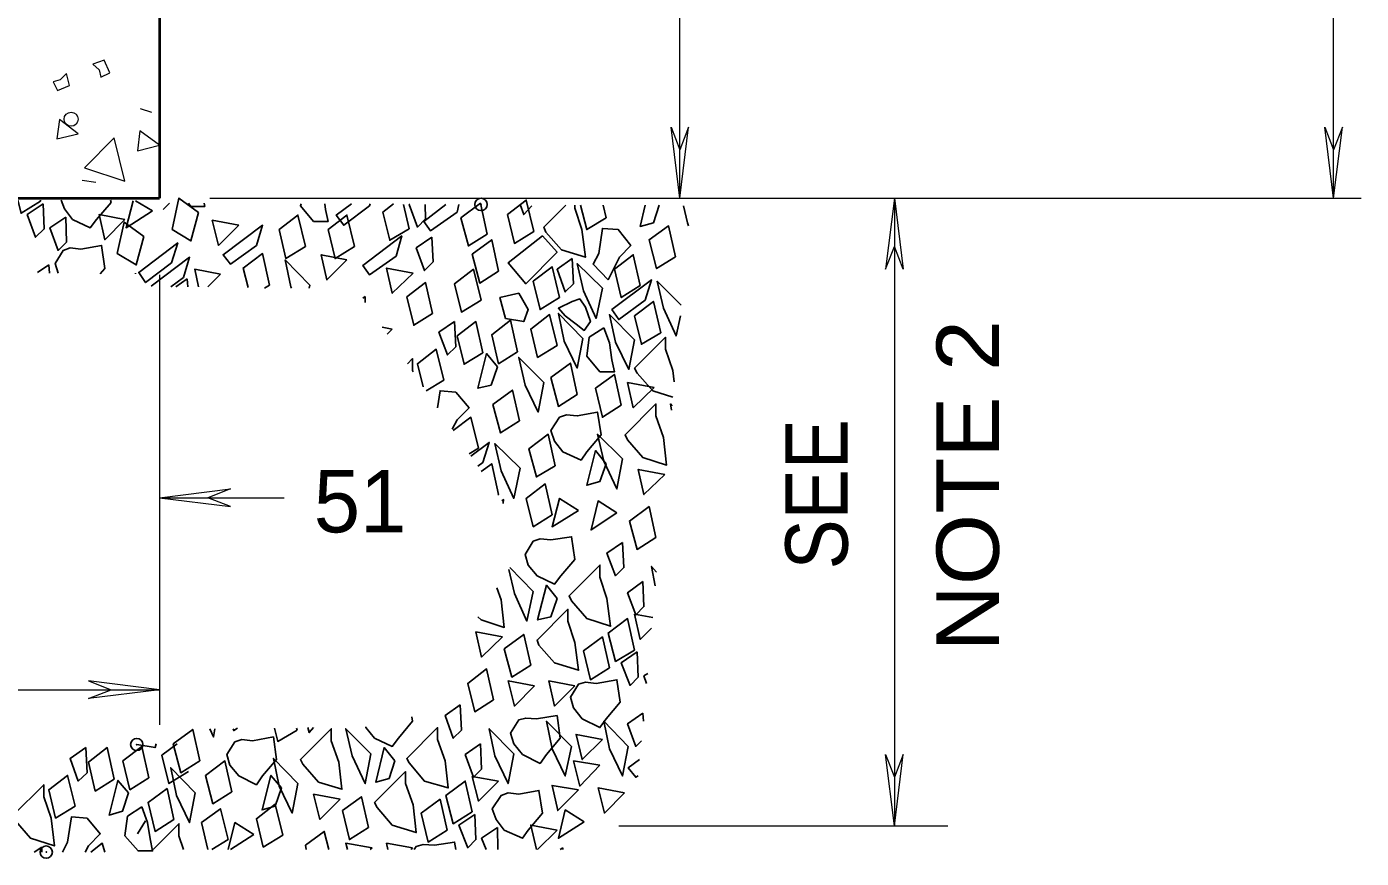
# Model space of a CAD drawing. Extents: x 312583 to 312854, y 144419 to 144597.
# Drawn here: x 312724.13 to 312740.39, y 144443.57 to 144453.7 of the extents above; entities that cross this region are included whole.
import ezdxf

# ---------------------------------------------------------------- set-up
doc = ezdxf.new("R2010")
doc.units = 0
doc.header["$LTSCALE"] = 0.3
doc.header["$PDMODE"] = 32
doc.header["$PDSIZE"] = 0.15
doc.layers.add('1', color=7, linetype='Continuous', lineweight=25)
doc.layers.add('2', color=7, linetype='Continuous', lineweight=13)

msp = doc.modelspace()

# ---------------------------------------------------------------- linework, layer by layer
at = {"layer": '1', "lineweight": 40}
for p in [(312725.751, 144497.14), (312697.001, 144451.6154)]:
    msp.add_line(p, (312725.751, 144451.6154), dxfattribs=at)
at = {"layer": '1'}
for p, q in [((312724.302, 144451.577), (312724.302, 144451.5924)), ((312725.4597, 144451.5847), (312725.6667, 144451.462)), ((312725.8737, 144451.554), (312725.797, 144451.4774)), ((312728.3194, 144451.5464), (312728.3117, 144451.5234)), ((312728.7947, 144451.2397), (312728.7257, 144451.5387)), ((312729.4004, 144451.5387), (312729.3774, 144451.4467)), ((312729.6687, 144451.5387), (312729.661, 144451.5387)), ((312730.811, 144451.531), (312730.811, 144451.4927)), ((312731.1944, 144451.3777), (312731.156, 144451.531)), ((312724.2637, 144450.7107), (312724.4017, 144450.8027)), ((312724.4017, 144450.8027), (312724.4094, 144450.703)), ((312725.4597, 144450.6954), (312725.4597, 144450.703)), ((312726.0424, 144450.6494), (312725.889, 144450.5344)), ((312726.4947, 144450.6877), (312726.3414, 144450.5344)), ((312725.9504, 144450.5344), (312726.0884, 144450.634)), ((312726.0884, 144450.634), (312726.096, 144450.5344)), ((312727.0314, 144450.519), (312727.0927, 144450.5574)), ((312727.5757, 144450.519), (312727.5834, 144450.5574)), ((312728.2274, 144450.3964), (312728.258, 144450.4194)), ((312728.258, 144450.4194), (312728.258, 144450.3427)), ((312728.465, 144450.0437), (312728.5877, 144450.0207)), ((312728.5877, 144450.0207), (312728.5264, 144449.9594)), ((312728.833, 144449.5147), (312728.8407, 144449.4994)), ((312729.0017, 144449.2694), (312729.2164, 144449.3997)), ((312731.8, 144448.9627), (312731.892, 144448.702)), ((312729.523, 144448.5027), (312729.638, 144448.5717)), ((312729.6917, 144448.3954), (312729.6304, 144448.3494)), ((312729.8757, 144447.9967), (312729.8834, 144448.0044)), ((312730.305, 144446.8237), (312730.0214, 144447.115)), ((312731.639, 144445.344), (312731.6467, 144445.2444)), ((312727.43, 144445.137), (312727.4224, 144445.16)), ((312725.4827, 144443.872), (312725.5824, 144444.033)), ((312725.9887, 144443.849), (312726.0424, 144443.6804)), ((312726.901, 144443.8644), (312726.6174, 144443.6804)), ((312729.868, 144443.9487), (312729.8757, 144443.6804)), ((312730.5964, 144443.918), (312730.3587, 144443.6804)), ((312724.2254, 144443.6497), (312724.3174, 144443.711)), ((312724.3174, 144443.711), (312724.3174, 144443.6497)), ((312726.3874, 144443.6804), (312726.5867, 144443.803)), ((312728.3424, 144443.7034), (312728.3194, 144443.6804)), ((312728.833, 144443.7034), (312728.8177, 144443.6804)), ((312730.6347, 144443.6804), (312730.6654, 144443.7034)), ((312730.6654, 144443.7034), (312730.6654, 144443.6804)), ((312724.3787, 144443.6497), (312724.371, 144443.6497))]:
    msp.add_line(p, q, dxfattribs=at)
for points in [[(312724.026, 144451.5924), (312724.0644, 144451.4314), (312724.302, 144451.577)], [(312724.9844, 144451.3547), (312724.9077, 144451.255), (312724.693, 144451.3547), (312724.5934, 144451.485), (312724.555, 144451.5924)], [(312725.153, 144451.5924), (312725.1607, 144451.5617), (312724.9844, 144451.3547)], [(312725.6667, 144451.462), (312725.3447, 144451.255), (312725.429, 144451.5847)], [(312726.2954, 144451.554), (312726.303, 144451.5157), (312726.1344, 144451.5157), (312726.1037, 144451.554)], [(312727.7674, 144451.5464), (312727.775, 144451.4774), (312727.8057, 144451.3317), (312727.6294, 144451.3317), (312727.4684, 144451.5234), (312727.476, 144451.5464)], [(312728.3117, 144451.5234), (312727.9974, 144451.2857), (312727.9054, 144451.4084), (312728.0894, 144451.5464)], [(312728.603, 144451.5464), (312728.4727, 144451.4467), (312728.557, 144451.1017), (312728.7947, 144451.2397)], [(312728.9864, 144451.5387), (312728.994, 144451.3624), (312728.8944, 144451.2627), (312728.7947, 144451.5387), (312728.8024, 144451.5387)], [(312729.3774, 144451.4467), (312729.0554, 144451.2167), (312728.971, 144451.3317), (312729.2394, 144451.5387)], [(312730.2897, 144451.5234), (312730.19, 144451.416), (312730.144, 144451.5387)], [(312730.811, 144451.4927), (312730.8954, 144451.232), (312730.9414, 144450.8947), (312730.65, 144450.9867), (312730.4584, 144451.2014), (312730.4354, 144451.2627), (312730.7037, 144451.531)], [(312730.88, 144451.531), (312730.9567, 144451.232), (312731.1944, 144451.3777)], [(312731.8384, 144451.531), (312731.7694, 144451.3164), (312731.6084, 144451.2704), (312731.6697, 144451.531)], [(312732.1374, 144451.5234), (312732.1834, 144451.3164), (312732.1987, 144451.278)], [(312724.5167, 144450.703), (312724.4784, 144450.818), (312724.578, 144450.979), (312724.6624, 144451.0097), (312724.7927, 144450.9944), (312725.0457, 144451.0404), (312725.084, 144450.7567), (312725.0304, 144450.6954)], [(312725.6514, 144450.542), (312726.119, 144450.8947), (312726.0424, 144450.6494)], [(312727.0927, 144450.5574), (312727.0084, 144450.9407), (312726.7707, 144450.7644), (312726.832, 144450.5267)], [(312727.5834, 144450.5574), (312727.2844, 144450.864), (312727.3534, 144450.5344), (312727.361, 144450.519)], [(312726.2264, 144450.5344), (312726.1804, 144450.749), (312726.4947, 144450.6877)], [(312732.1067, 144450.312), (312731.8154, 144450.6034), (312731.892, 144450.2737), (312732.0454, 144449.9364), (312732.099, 144450.1817)], [(312732.007, 144449.1927), (312731.7617, 144449.2694), (312731.57, 144449.484), (312731.5394, 144449.5454), (312731.915, 144449.921), (312731.915, 144449.7754)], [(312729.2164, 144449.3997), (312729.1244, 144449.7754), (312728.8944, 144449.599), (312728.9634, 144449.3154)], [(312731.915, 144449.7754), (312732.007, 144449.5147), (312732.0224, 144449.3767)], [(312728.7717, 144449.599), (312728.833, 144449.6604), (312728.833, 144449.5147)], [(312729.316, 144448.8017), (312729.3774, 144448.9167), (312729.523, 144449.0624), (312729.362, 144449.254), (312729.1704, 144449.2694), (312729.1397, 144449.0624)], [(312731.9304, 144448.3647), (312731.9304, 144448.3647), (312731.639, 144448.4567), (312731.455, 144448.6714), (312731.4244, 144448.7327), (312731.8, 144449.1084), (312731.8, 144448.9627)], [(312731.9994, 144449.0854), (312731.9764, 144449.1084), (312731.9917, 144449.0317)], [(312729.638, 144448.5717), (312729.546, 144448.9474), (312729.3314, 144448.7864)], [(312731.892, 144448.702), (312731.9304, 144448.3647), (312731.9304, 144448.3647)], [(312729.546, 144448.472), (312729.7684, 144448.6407), (312729.6917, 144448.3954)], [(312729.8834, 144448.0044), (312729.799, 144448.38), (312729.6687, 144448.288)], [(312729.9217, 144447.9277), (312729.9447, 144447.943), (312729.937, 144447.897)], [(312730.006, 144447.092), (312730.075, 144446.8007), (312730.2284, 144446.4634), (312730.305, 144446.8237)], [(312731.8077, 144447.0614), (312731.7464, 144447.1304), (312731.7924, 144446.8927)], [(312729.8604, 144446.8697), (312729.914, 144446.724), (312729.9524, 144446.3867), (312729.6687, 144446.4787), (312729.6304, 144446.517)], [(312731.7464, 144446.379), (312731.6084, 144446.241), (312731.5394, 144446.5477), (312731.7617, 144446.5094)], [(312731.685, 144445.7044), (312731.6544, 144445.7964), (312731.7004, 144445.827)], [(312728.8254, 144445.298), (312728.833, 144445.2444), (312728.6644, 144445.0374)], [(312731.6237, 144445.0067), (312731.5547, 144444.9377), (312731.455, 144445.2137), (312731.639, 144445.344)], [(312726.3644, 144445.1524), (312726.4104, 144445.0527), (312726.4257, 144445.1524)], [(312726.648, 144445.1524), (312726.6557, 144445.1294), (312726.7017, 144445.16)], [(312727.154, 144445.16), (312727.1924, 144444.999), (312727.43, 144445.137)], [(312727.6294, 144445.1677), (312727.5757, 144445.1064), (312727.5604, 144445.1677)], [(312728.6644, 144445.0374), (312728.5877, 144444.9377), (312728.373, 144445.0374), (312728.2657, 144445.1677), (312728.2657, 144445.1754)], [(312725.7127, 144444.9684), (312725.6974, 144444.9224), (312725.475, 144444.9607)], [(312725.9657, 144444.9684), (312725.7817, 144444.8304), (312725.866, 144444.4854), (312726.1037, 144444.631)], [(312731.5854, 144444.5774), (312731.5547, 144444.562), (312731.4627, 144444.677), (312731.6007, 144444.7767)], [(312726.5867, 144443.803), (312726.4947, 144444.1787), (312726.2647, 144444.01), (312726.3414, 144443.6804)], [(312724.8464, 144443.6497), (312724.8847, 144443.7264), (312725.0304, 144443.872), (312724.8694, 144444.0637), (312724.6777, 144444.079), (312724.6317, 144443.7724), (312724.5704, 144443.6497)], [(312725.6744, 144443.6804), (312725.9887, 144443.9947), (312725.9887, 144443.849)], [(312726.5867, 144443.6804), (312726.671, 144444.01), (312726.901, 144443.8644)], [(312727.8134, 144443.6804), (312727.7597, 144443.9027), (312727.5297, 144443.734), (312727.5374, 144443.6804)], [(312729.73, 144443.6804), (312729.6764, 144443.8184), (312729.868, 144443.9487)], [(312730.3434, 144443.6804), (312730.2744, 144443.9794), (312730.5964, 144443.918)], [(312725.084, 144443.6497), (312725.0534, 144443.757), (312724.9154, 144443.6497)], [(312728.0434, 144443.6804), (312728.0204, 144443.757), (312728.3424, 144443.7034)], [(312728.534, 144443.6804), (312728.5187, 144443.757), (312728.833, 144443.7034)], [(312728.856, 144443.6804), (312728.879, 144443.7187), (312728.9634, 144443.7417), (312729.1014, 144443.734), (312729.3467, 144443.7724), (312729.362, 144443.6804)]]:
    msp.add_lwpolyline(points, dxfattribs=at)
for points in [[(312724.3327, 144451.5464), (312724.348, 144451.2397), (312724.2407, 144451.14), (312724.141, 144451.416)], [(312725.9044, 144451.232), (312725.9887, 144451.6154), (312726.2264, 144451.439), (312726.1344, 144451.094)], [(312729.7454, 144451.1784), (312729.661, 144451.554), (312729.4234, 144451.3777), (312729.5154, 144451.0327)], [(312730.3127, 144451.209), (312730.2207, 144451.5924), (312729.9907, 144451.416), (312730.075, 144451.0634)], [(312724.6087, 144451.3854), (312724.6164, 144451.0787), (312724.5167, 144450.979), (312724.417, 144451.255)], [(312725.3294, 144451.3547), (312725.084, 144451.1094), (312725.015, 144451.416)], [(312725.2374, 144450.9407), (312725.3217, 144451.324), (312725.5594, 144451.1477), (312725.4674, 144450.8027)], [(312726.717, 144451.2857), (312726.4717, 144451.0404), (312726.395, 144451.347)], [(312727.5297, 144451.025), (312727.4377, 144451.4084), (312727.2077, 144451.232), (312727.292, 144450.8794)], [(312728.1277, 144451.025), (312728.0357, 144451.4084), (312727.8057, 144451.232), (312727.89, 144450.8794)], [(312726.9317, 144451.0404), (312726.6174, 144450.8104), (312726.5254, 144450.9254), (312727.0084, 144451.2857)], [(312728.6337, 144450.91), (312728.3117, 144450.68), (312728.2274, 144450.795), (312728.7027, 144451.1554)], [(312729.0707, 144451.14), (312729.086, 144450.841), (312728.9787, 144450.7337), (312728.879, 144451.0097)], [(312730.42, 144451.1554), (312730.5964, 144450.956), (312730.213, 144450.5727), (312729.9984, 144450.8257)], [(312731.2174, 144450.6187), (312731.3554, 144450.8947), (312731.4934, 144451.0404), (312731.34, 144451.232), (312731.1484, 144451.2474), (312731.1024, 144450.9407), (312731.0334, 144450.8104)], [(312732.0377, 144450.9024), (312731.9534, 144451.278), (312731.7157, 144451.1094), (312731.8077, 144450.7567)], [(312725.8967, 144450.8257), (312725.5824, 144450.588), (312725.498, 144450.7107), (312725.9734, 144451.071)], [(312729.8834, 144450.726), (312729.799, 144451.1094), (312729.5614, 144450.933), (312729.6534, 144450.5804)], [(312728.0357, 144450.864), (312727.7904, 144450.6187), (312727.7214, 144450.9254)], [(312730.7804, 144450.8794), (312730.7957, 144450.5727), (312730.696, 144450.473), (312730.5964, 144450.749)], [(312731.1484, 144450.519), (312730.8417, 144450.818), (312730.9184, 144450.4884), (312731.0717, 144450.151)], [(312731.6084, 144450.5497), (312731.524, 144450.9254), (312731.294, 144450.749), (312731.3784, 144450.404)], [(312728.8407, 144450.703), (312728.5877, 144450.4577), (312728.5187, 144450.7644)], [(312729.6687, 144450.3734), (312729.5767, 144450.749), (312729.3467, 144450.5727), (312729.431, 144450.2277)], [(312730.627, 144450.404), (312730.535, 144450.7797), (312730.305, 144450.6034), (312730.3894, 144450.2584)], [(312729.0784, 144450.2124), (312728.994, 144450.588), (312728.764, 144450.4117), (312728.8484, 144450.0667)], [(312731.6697, 144450.3734), (312731.3477, 144450.1357), (312731.2634, 144450.2584), (312731.7464, 144450.6187)], [(312730.1287, 144450.4577), (312730.2437, 144450.2584), (312730.19, 144450.1127), (312729.9677, 144450.151), (312729.8987, 144450.404)], [(312730.7804, 144450.358), (312730.8724, 144450.3887), (312730.9414, 144450.289), (312731.0027, 144450.1127), (312730.926, 144450.0054), (312730.8264, 144450.082), (312730.696, 144450.1817), (312730.6117, 144450.2737)], [(312731.8614, 144449.9747), (312731.7694, 144450.358), (312731.5394, 144450.1817), (312731.6237, 144449.8367)], [(312730.5964, 144449.8214), (312730.5044, 144450.197), (312730.2744, 144450.0207), (312730.3587, 144449.6757)], [(312730.9107, 144449.9057), (312730.6117, 144450.2124), (312730.6807, 144449.875), (312730.8417, 144449.5454)], [(312731.5394, 144449.8904), (312731.2327, 144450.197), (312731.3094, 144449.8597), (312731.4704, 144449.53)], [(312729.3467, 144450.1127), (312729.362, 144449.806), (312729.2624, 144449.7064), (312729.155, 144449.9824)], [(312729.6917, 144449.7294), (312729.6074, 144450.1127), (312729.3774, 144449.9364), (312729.4617, 144449.5914)], [(312730.1134, 144449.7447), (312730.029, 144450.128), (312729.799, 144449.9517), (312729.8834, 144449.599)], [(312731.1637, 144450.036), (312731.2327, 144449.852), (312731.2634, 144449.645), (312731.294, 144449.4994), (312731.1177, 144449.4994), (312730.9567, 144449.691), (312730.9874, 144449.921)], [(312729.868, 144449.5607), (312729.7914, 144449.3384), (312729.6304, 144449.3), (312729.7377, 144449.7217)], [(312730.4354, 144449.369), (312730.1287, 144449.6757), (312730.2054, 144449.3384), (312730.3664, 144449.0087)], [(312730.8417, 144449.2234), (312730.7574, 144449.6067), (312730.5197, 144449.4304), (312730.6117, 144449.0777)], [(312731.3784, 144449.093), (312731.294, 144449.4687), (312731.064, 144449.3), (312731.1484, 144448.9474)], [(312731.777, 144449.3077), (312731.524, 144449.0624), (312731.455, 144449.369)], [(312730.1364, 144448.9014), (312730.052, 144449.277), (312729.8144, 144449.1007), (312729.9064, 144448.7557)], [(312730.9567, 144448.5257), (312730.8877, 144448.426), (312730.6654, 144448.5257), (312730.5657, 144448.656), (312730.5197, 144448.7864), (312730.627, 144448.9474), (312730.7114, 144448.978), (312730.8417, 144448.9627), (312731.087, 144449.0087), (312731.133, 144448.7327)], [(312730.5734, 144448.357), (312730.489, 144448.7404), (312730.2514, 144448.564), (312730.3434, 144448.219)], [(312731.3937, 144448.4414), (312731.087, 144448.7404), (312731.1637, 144448.4107), (312731.3247, 144448.0734)], [(312730.144, 144448.3264), (312729.8374, 144448.6254), (312729.914, 144448.2957), (312730.0674, 144447.9584)], [(312731.1944, 144448.38), (312731.1177, 144448.1654), (312730.9567, 144448.1194), (312731.064, 144448.541)], [(312731.9074, 144448.2497), (312731.6544, 144448.0044), (312731.5854, 144448.311)], [(312730.535, 144447.759), (312730.4507, 144448.1347), (312730.2207, 144447.9584), (312730.305, 144447.6134)], [(312730.857, 144447.8127), (312730.535, 144447.6134), (312730.627, 144447.9584)], [(312731.3247, 144447.782), (312731.0104, 144447.575), (312731.0947, 144447.9277)], [(312731.8, 144447.483), (312731.7157, 144447.8587), (312731.478, 144447.6824), (312731.57, 144447.3374)], [(312730.6424, 144447.0154), (312730.5657, 144446.9157), (312730.351, 144447.0154), (312730.2437, 144447.1457), (312730.2054, 144447.276), (312730.305, 144447.437), (312730.3894, 144447.4677), (312730.5197, 144447.4524), (312730.7727, 144447.4907), (312730.811, 144447.2147)], [(312731.3937, 144447.4217), (312731.409, 144447.115), (312731.3094, 144447.0154), (312731.202, 144447.2914)], [(312731.1177, 144447), (312731.202, 144446.7394), (312731.248, 144446.402), (312730.9567, 144446.494), (312730.7727, 144446.7087), (312730.742, 144446.77), (312731.1177, 144447.1457)], [(312731.639, 144446.9464), (312731.6544, 144446.6397), (312731.5547, 144446.54), (312731.455, 144446.8084)], [(312730.5964, 144446.7394), (312730.5197, 144446.517), (312730.3587, 144446.4787), (312730.466, 144446.9004)], [(312730.7267, 144446.4634), (312730.811, 144446.2027), (312730.857, 144445.8654), (312730.5657, 144445.9574), (312730.374, 144446.172), (312730.351, 144446.2334), (312730.7267, 144446.609)], [(312731.5394, 144446.1107), (312731.455, 144446.494), (312731.2174, 144446.3177), (312731.3094, 144445.9727)], [(312729.9294, 144446.2717), (312729.6764, 144446.0264), (312729.6074, 144446.333)], [(312730.2744, 144445.9267), (312730.19, 144446.3024), (312729.9524, 144446.126), (312730.0444, 144445.781)], [(312731.2327, 144445.896), (312731.1484, 144446.2717), (312730.9184, 144446.103), (312731.0027, 144445.7504)], [(312731.57, 144446.0877), (312731.5854, 144445.781), (312731.4857, 144445.6814), (312731.3784, 144445.9574)], [(312729.822, 144445.505), (312729.7377, 144445.8807), (312729.5077, 144445.7044), (312729.592, 144445.3594)], [(312730.3204, 144445.6737), (312730.075, 144445.4284), (312729.9984, 144445.735)], [(312730.811, 144445.6737), (312730.5657, 144445.4284), (312730.4967, 144445.735)], [(312731.1944, 144445.275), (312731.1177, 144445.1677), (312730.903, 144445.275), (312730.7957, 144445.4054), (312730.7574, 144445.5357), (312730.857, 144445.6967), (312730.9414, 144445.7197), (312731.0717, 144445.7044), (312731.3247, 144445.7504), (312731.363, 144445.4744)], [(312729.4157, 144445.4437), (312729.431, 144445.137), (312729.3314, 144445.0374), (312729.2317, 144445.3134)], [(312730.466, 144444.838), (312730.3894, 144444.7307), (312730.1747, 144444.838), (312730.0674, 144444.9684), (312730.029, 144445.0987), (312730.1287, 144445.2597), (312730.213, 144445.2827), (312730.3434, 144445.275), (312730.5964, 144445.3134), (312730.6347, 144445.0374)], [(312726.2417, 144444.7614), (312726.1574, 144445.1447), (312725.9197, 144444.9684), (312726.0117, 144444.6157)], [(312727.844, 144445.0067), (312727.936, 144444.746), (312727.9744, 144444.4164), (312727.6907, 144444.5007), (312727.499, 144444.723), (312727.4684, 144444.7767), (312727.844, 144445.1524)], [(312728.327, 144444.8457), (312728.0204, 144445.1524), (312728.097, 144444.8227), (312728.258, 144444.4854)], [(312729.1397, 144445.022), (312729.2317, 144444.7614), (312729.27, 144444.4317), (312728.9787, 144444.516), (312728.7947, 144444.7384), (312728.764, 144444.792), (312729.1397, 144445.1677)], [(312730.0674, 144444.8457), (312729.7684, 144445.1524), (312729.8374, 144444.8227), (312729.9984, 144444.4854)], [(312730.7727, 144444.9377), (312730.466, 144445.2444), (312730.535, 144444.907), (312730.696, 144444.5774)], [(312731.4627, 144444.9377), (312731.1637, 144445.2444), (312731.2327, 144444.907), (312731.3937, 144444.5774)], [(312727.0084, 144444.5774), (312726.9317, 144444.47), (312726.717, 144444.5774), (312726.6097, 144444.7077), (312726.5714, 144444.838), (312726.671, 144444.9914), (312726.7554, 144445.022), (312726.8857, 144445.0067), (312727.1387, 144445.0527), (312727.177, 144444.7767)], [(312729.661, 144444.9684), (312729.6764, 144444.6617), (312729.5767, 144444.562), (312729.477, 144444.838)], [(312731.1484, 144445.022), (312730.903, 144444.7767), (312730.8264, 144445.0834)], [(312724.854, 144444.9224), (312724.8694, 144444.6157), (312724.762, 144444.516), (312724.6624, 144444.792)], [(312725.199, 144444.539), (312725.1147, 144444.9224), (312724.8847, 144444.746), (312724.969, 144444.3934)], [(312725.6207, 144444.5544), (312725.5364, 144444.9377), (312725.3064, 144444.7614), (312725.3907, 144444.4087)], [(312728.6184, 144444.7614), (312728.5494, 144444.5467), (312728.3884, 144444.5007), (312728.488, 144444.9224)], [(312726.188, 144444.3704), (312725.889, 144444.677), (312725.958, 144444.3397), (312726.119, 144444.01)], [(312726.6327, 144444.3857), (312726.5484, 144444.7614), (312726.3107, 144444.585), (312726.4027, 144444.24)], [(312727.4377, 144444.4854), (312727.1387, 144444.792), (312727.2077, 144444.4547), (312727.3687, 144444.125)], [(312728.7487, 144444.4854), (312728.8407, 144444.2247), (312728.879, 144443.8874), (312728.5877, 144443.9794), (312728.4037, 144444.194), (312728.373, 144444.2554), (312728.7487, 144444.631)], [(312731.1177, 144444.7077), (312730.8724, 144444.4547), (312730.7957, 144444.7614)], [(312724.3404, 144444.3244), (312724.4324, 144444.0637), (312724.4707, 144443.7264), (312724.1794, 144443.8184), (312723.9954, 144444.033), (312723.9647, 144444.0944), (312724.3404, 144444.47)], [(312724.7237, 144444.2094), (312724.6317, 144444.585), (312724.4017, 144444.4087), (312724.486, 144444.0637)], [(312725.3754, 144444.3704), (312725.2987, 144444.148), (312725.1377, 144444.102), (312725.245, 144444.5237)], [(312727.2384, 144444.4317), (312727.1617, 144444.2094), (312727.0007, 144444.1634), (312727.108, 144444.585)], [(312729.5614, 144444.1404), (312729.477, 144444.516), (312729.2394, 144444.3397), (312729.3314, 144443.9947)], [(312729.8834, 144444.516), (312729.638, 144444.2707), (312729.5614, 144444.5697)], [(312725.9274, 144444.0484), (312725.843, 144444.424), (312725.613, 144444.2554), (312725.6974, 144443.9027)], [(312727.9514, 144444.2937), (312727.706, 144444.0484), (312727.6294, 144444.355)], [(312728.2964, 144443.9487), (312728.212, 144444.3244), (312727.982, 144444.1557), (312728.0664, 144443.803)], [(312730.2437, 144443.918), (312730.1747, 144443.8184), (312729.9524, 144443.918), (312729.8527, 144444.0484), (312729.8067, 144444.1787), (312729.914, 144444.3397), (312729.9984, 144444.3704), (312730.1287, 144444.355), (312730.374, 144444.401), (312730.42, 144444.125)], [(312730.857, 144444.4087), (312730.604, 144444.1557), (312730.535, 144444.4624)], [(312731.4167, 144444.3704), (312731.1714, 144444.125), (312731.0947, 144444.4317)], [(312725.5364, 144444.2017), (312725.6054, 144444.01), (312725.636, 144443.8107), (312725.6667, 144443.665), (312725.4904, 144443.665), (312725.3294, 144443.849), (312725.36, 144444.0867)], [(312727.2537, 144443.8567), (312727.1617, 144444.2324), (312726.9317, 144444.056), (312727.016, 144443.711)], [(312729.2547, 144443.918), (312729.1704, 144444.2937), (312728.9404, 144444.125), (312729.0247, 144443.7724)], [(312730.926, 144444.0177), (312730.6117, 144443.8184), (312730.696, 144444.1634)], [(312729.592, 144444.1097), (312729.6074, 144443.803), (312729.5077, 144443.7034), (312729.4004, 144443.9794)]]:
    msp.add_lwpolyline(points, close=True, dxfattribs=at)
for p in [(312729.6687, 144451.5387), (312725.475, 144444.9607), (312724.371, 144443.6497)]:
    msp.add_point(p, dxfattribs=at)
at = {"layer": '2'}
for p, q in [((312740.057, 144451.6154), (312740.057, 144497.6154)), ((312725.659, 144452.658), (312725.521, 144452.704)), ((312731.984, 144452.4817), (312732.0914, 144452.2057)), ((312732.0914, 144451.6154), (312731.984, 144452.4817)), ((312732.1987, 144452.4817), (312732.0914, 144452.2057)), ((312732.0914, 144451.6154), (312732.1987, 144452.4817)), ((312739.9497, 144452.4817), (312740.057, 144452.2057)), ((312740.057, 144451.6154), (312739.9497, 144452.4817)), ((312740.1644, 144452.4817), (312740.057, 144452.2057)), ((312740.057, 144451.6154), (312740.1644, 144452.4817)), ((312724.9767, 144451.807), (312724.808, 144451.83)), ((312726.3644, 144451.6154), (312740.3944, 144451.6154)), ((312734.7057, 144451.6154), (312734.5984, 144450.749)), ((312734.7057, 144451.6154), (312734.7057, 144443.9717)), ((312734.7057, 144451.6154), (312734.813, 144450.749)), ((312734.5984, 144450.749), (312734.7057, 144451.025)), ((312734.813, 144450.749), (312734.7057, 144451.025)), ((312725.751, 144450.68), (312725.751, 144445.1984)), ((312725.751, 144447.966), (312726.6174, 144448.0734)), ((312726.6174, 144448.0734), (312726.3414, 144447.966)), ((312725.751, 144447.966), (312727.269, 144447.966)), ((312725.751, 144447.966), (312726.6174, 144447.8587)), ((312726.6174, 144447.8587), (312726.3414, 144447.966)), ((312719.2804, 144445.6277), (312725.751, 144445.6277)), ((312724.8847, 144445.735), (312725.1607, 144445.6277)), ((312725.751, 144445.6277), (312724.8847, 144445.735)), ((312724.8847, 144445.5204), (312725.1607, 144445.6277)), ((312725.751, 144445.6277), (312724.8847, 144445.5204)), ((312734.5984, 144444.838), (312734.7057, 144444.562)), ((312734.7057, 144443.9717), (312734.5984, 144444.838)), ((312734.813, 144444.838), (312734.7057, 144444.562)), ((312734.7057, 144443.9717), (312734.813, 144444.838)), ((312731.3477, 144443.9717), (312735.3574, 144443.9717))]:
    msp.add_line(p, q, dxfattribs=at)
msp.add_lwpolyline([(312732.0914, 144451.6154), (312732.0914, 144457.3654), (312732.0914, 144463.1154)], dxfattribs=at)
for points in [[(312725.015, 144453.1794), (312725.038, 144453.0874), (312725.1454, 144453.141), (312725.0764, 144453.2944), (312724.9384, 144453.2484)], [(312724.5397, 144453.0567), (312724.4554, 144453.0337), (312724.509, 144452.9264), (312724.6547, 144452.9877), (312724.6164, 144453.1334)], [(312724.532, 144452.5737), (312724.5014, 144452.336), (312724.762, 144452.3974)], [(312725.199, 144452.3514), (312724.8387, 144451.9834), (312725.3294, 144451.8224)], [(312725.5134, 144452.4357), (312725.4827, 144452.1904), (312725.751, 144452.2594)]]:
    msp.add_lwpolyline(points, close=True, dxfattribs=at)
msp.add_circle((312724.6745, 144452.5769), 0.0865, dxfattribs=at)

# ---------------------------------------------------------------- texts
for s, width, p in [('NOTE 2', 1.1, (312735.9783, 144446.094)), ('SEE', 0.9, (312734.137, 144447.0931))]:
    msp.add_text(s, height=0.76, rotation=90, dxfattribs=dict(at, width=width)).set_placement(p)
msp.add_text('51 ', height=0.76, dxfattribs=at).set_placement((312727.6305, 144447.5448))

doc.saveas('drawing.dxf')
